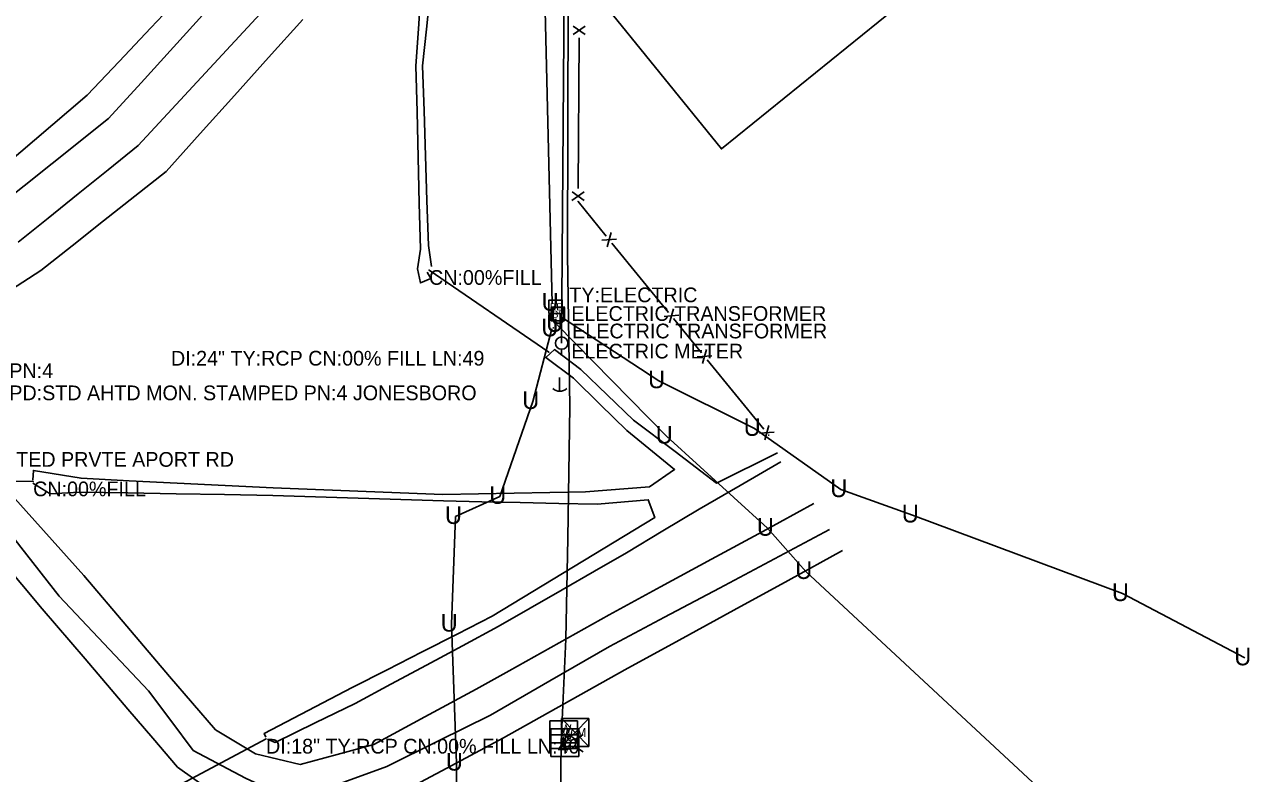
# Model space of a CAD drawing. Extents: x 1707085 to 1720058, y 548761 to 560063.
# Drawn here: x 1712315.3 to 1712731.2, y 549372.3 to 549626.7 of the extents above; entities that cross this region are included whole.
import ezdxf

# ---------------------------------------------------------------- set-up
doc = ezdxf.new("R2010")
doc.units = 0
for name, color, linetype in [('3', 7, 'Continuous'), ('Default', 7, 'Continuous'), ('R_Contours', 7, 'Continuous'), ('R_Water Annot', 7, 'Continuous'), ('S_BUILDING', 7, 'Continuous'), ('S_DRG_PT_SYM', 7, 'Continuous'), ('S_EDGE_PAVEMENT', 7, 'Continuous'), ('S_ELECTRIC_UTILITIES', 7, 'Continuous'), ('S_MISC_STRUCTURES_ANNOT', 7, 'Continuous'), ('S_MSC_PT_SYM', 7, 'Continuous'), ('S_PAVEMENT_CROWN', 7, 'Continuous'), ('S_PRIMARY_CTL_ANNOT', 7, 'Continuous'), ('S_SIDE_DRAIN_ANNOT', 7, 'Continuous'), ('S_STR_PT_SYM', 7, 'Continuous'), ('S_SURVEY_TEXT_ANNOT', 7, 'Continuous'), ('S_UNDERGROUND_CABLE', 7, 'Continuous'), ('S_UNDERGROUND_CABLE_ANNOT', 7, 'Continuous'), ('S_UTILITY_POLE', 7, 'Continuous'), ('S_UTL_PT_SYM', 7, 'Continuous')]:
    doc.layers.add(name, color=color, linetype=linetype)

msp = doc.modelspace()

# ---------------------------------------------------------------- linework, layer by layer
for points in [[(1712477.33, 549715.78), (1712472.54, 549696.84), (1712465.4, 549684), (1712458.27, 549671.17), (1712452.94, 549675.14), (1712451.45, 549674.62), (1712451.65, 549662.89), (1712450.79, 549650.32), (1712449.93, 549637.76), (1712449.06, 549625.19), (1712448.2, 549612.62), (1712448.59, 549597.08), (1712448.99, 549581.53), (1712449.38, 549565.99), (1712449.77, 549550.44), (1712448.78, 549543.69), (1712449.73, 549538.92), (1712453.33, 549540.43), (1712452.04, 549542.59)], [(1712482.85, 549714.24), (1712476.5, 549696.41), (1712466.06, 549679.47), (1712455.63, 549662.54), (1712454.35, 549650.06), (1712453.07, 549637.58), (1712451.79, 549625.11), (1712450.51, 549612.63), (1712451, 549597.38), (1712451.49, 549582.13), (1712451.98, 549566.87), (1712452.48, 549551.62), (1712453.51, 549544.5)], [(1712369.03, 549636.94), (1712358.25, 549625.52), (1712347.46, 549614.09), (1712336.67, 549602.67), (1712318.76, 549587.45), (1712300.85, 549572.22)], [(1712318.16, 549471.87), (1712318.37, 549475.26), (1712334.57, 549472.55), (1712350.86, 549471.75), (1712367.16, 549470.95), (1712383.46, 549470.15), (1712399.76, 549469.35), (1712414.15, 549468.78), (1712428.54, 549468.2), (1712442.93, 549467.63), (1712457.32, 549467.06), (1712481.54, 549467.54), (1712505.76, 549468.01), (1712527.51, 549469.62), (1712536.03, 549475.56), (1712519.8, 549488.74), (1712510.74, 549497.64), (1712501.67, 549506.55), (1712492.28, 549513.55), (1712495.32, 549516.26), (1712504.19, 549509.48), (1712522.12, 549492.35), (1712536.2, 549481.64), (1712550.27, 549470.93), (1712571.02, 549481.17)], [(1712572.1, 549478.15), (1712558.27, 549470.1), (1712544.43, 549462.04), (1712532.07, 549454.66), (1712519.7, 549447.29), (1712508.81, 549441.01), (1712497.91, 549434.73), (1712487.02, 549428.45), (1712476.13, 549422.17), (1712464, 549415.65), (1712451.87, 549409.13), (1712439.74, 549402.61), (1712427.62, 549396.1), (1712414.02, 549389.48), (1712400.42, 549382.86), (1712397.78, 549383.93)], [(1712318.21, 549470.9), (1712324.01, 549467.32), (1712334.01, 549467.9), (1712350.42, 549467.6), (1712366.83, 549467.31), (1712383.23, 549467.01), (1712399.64, 549466.72), (1712414.11, 549466.27), (1712428.59, 549465.82), (1712443.07, 549465.37), (1712457.54, 549464.92), (1712470.59, 549464.62), (1712483.64, 549464.33), (1712496.69, 549464.04), (1712509.74, 549463.75), (1712527.1, 549465.27), (1712529.29, 549459.19), (1712515.51, 549450.81), (1712501.73, 549442.44), (1712487.94, 549434.06), (1712474.16, 549425.68), (1712462.28, 549419.64), (1712450.39, 549413.6), (1712438.5, 549407.56), (1712426.61, 549401.53), (1712411.65, 549393.7), (1712396.69, 549385.87), (1712397.31, 549384.67)]]:
    msp.add_lwpolyline(points)
at = {"layer": '3'}
for p, q in [((1712493.34, 549515.39), (1712452.67, 549543.27)), ((1712273.3, 549472.1), (1712318.27, 549471.46)), ((1712397.33, 549384.07), (1712361.92, 549365.14))]:
    msp.add_line(p, q, dxfattribs=at)
at = {"layer": 'R_Contours'}
for p, q in [((1712505.68, 549626.11), (1712501.57, 549623.27)), ((1712501.59, 549626.14), (1712505.66, 549623.25)), ((1712505.32, 549569.81), (1712501.21, 549566.97)), ((1712501.23, 549569.83), (1712505.31, 549566.94)), ((1712514.5, 549556.02), (1712513.14, 549551.21)), ((1712511.32, 549553.43), (1712516.31, 549553.8)), ((1712535.62, 549530.14), (1712534.26, 549525.33)), ((1712532.45, 549527.55), (1712537.43, 549527.92)), ((1712543.7, 549513.76), (1712548.68, 549514.13)), ((1712546.87, 549516.35), (1712545.51, 549511.54)), ((1712564.82, 549487.88), (1712569.8, 549488.25)), ((1712567.99, 549490.47), (1712566.63, 549485.66))]:
    msp.add_line(p, q, dxfattribs=at)
for points in [[(1712503.61, 549622.13), (1712503.28, 549570.95)], [(1712503.26, 549566.55), (1712512.86, 549554.79)], [(1712514.78, 549552.44), (1712533.98, 549528.91)], [(1712535.63, 549526.89), (1712545.23, 549515.12)], [(1712547.15, 549512.77), (1712566.35, 549489.24)]]:
    msp.add_lwpolyline(points, dxfattribs=at)
at = {"layer": 'R_Water Annot'}
for p, q in [((1712499.89, 549641.55), (1712499.65, 549548.57)), ((1712499.65, 549548.57), (1712500.51, 549496.81)), ((1712500.51, 549496.81), (1712499.75, 549452.23)), ((1712499.75, 549452.23), (1712499.07, 549417.92)), ((1712499.07, 549417.92), (1712497.57, 549383.08)), ((1712493.7, 549390.15), (1712503.12, 549390.15)), ((1712493.7, 549380.73), (1712493.7, 549390.15)), ((1712497.62, 549390.95), (1712506.96, 549390.95)), ((1712497.62, 549390.95), (1712497.62, 549381.46)), ((1712497.62, 549390.95), (1712506.96, 549381.46)), ((1712506.96, 549390.95), (1712497.62, 549381.46)), ((1712503.12, 549390.15), (1712503.12, 549380.73)), ((1712506.96, 549390.95), (1712506.96, 549381.46)), ((1712493.7, 549385.46), (1712503.12, 549385.46)), ((1712494.07, 549387.43), (1712503.48, 549387.43)), ((1712494.07, 549378.02), (1712494.07, 549387.43)), ((1712502.19, 549383.85), (1712505.01, 549385.58)), ((1712503.48, 549387.43), (1712503.48, 549378.02)), ((1712503.12, 549380.73), (1712493.7, 549380.73)), ((1712494.07, 549382.74), (1712503.48, 549382.74)), ((1712497.57, 549383.08), (1712496.4, 549273.84)), ((1712497.62, 549381.46), (1712506.96, 549381.46)), ((1712502.07, 549381.54), (1712504.98, 549379.61)), ((1712503.48, 549378.02), (1712494.07, 549378.02))]:
    msp.add_line(p, q, dxfattribs=at)
msp.add_circle((1712500.29, 549382.79), 2.18, dxfattribs=at)
at = {"layer": 'S_BUILDING'}
for p, q in [((1712551.91, 549584.43), (1712648.77, 549662.87)), ((1712508.82, 549637.74), (1712551.91, 549584.43))]:
    msp.add_line(p, q, dxfattribs=at)
at = {"layer": 'S_DRG_PT_SYM'}
for points in [[(1712452.67, 549543.27), (1712452.67, 549543.32), (1712452.67, 549543.27), (1712452.62, 549543.27), (1712452.67, 549543.27), (1712452.67, 549543.22), (1712452.67, 549543.27), (1712452.72, 549543.27)], [(1712493.34, 549515.39), (1712493.34, 549515.44), (1712493.34, 549515.39), (1712493.29, 549515.39), (1712493.34, 549515.39), (1712493.34, 549515.34), (1712493.34, 549515.39), (1712493.39, 549515.39)], [(1712318.27, 549471.46), (1712318.27, 549471.51), (1712318.27, 549471.46), (1712318.22, 549471.46), (1712318.27, 549471.46), (1712318.27, 549471.41), (1712318.27, 549471.46), (1712318.32, 549471.46)], [(1712397.33, 549384.07), (1712397.33, 549384.12), (1712397.33, 549384.07), (1712397.28, 549384.07), (1712397.33, 549384.07), (1712397.33, 549384.02), (1712397.33, 549384.07), (1712397.38, 549384.07)]]:
    msp.add_lwpolyline(points, dxfattribs=at)
at = {"layer": 'S_EDGE_PAVEMENT'}
for points in [[(1712376.86, 549631.06), (1712365.88, 549618.95), (1712354.89, 549606.84), (1712343.9, 549594.73), (1712324.74, 549579.52), (1712305.58, 549564.31)], [(1712376.86, 549631.06), (1712365.88, 549618.95), (1712354.89, 549606.84), (1712343.9, 549594.73), (1712324.74, 549579.52), (1712305.58, 549564.31)], [(1712409.78, 549628.4), (1712398.19, 549615.5), (1712386.6, 549602.6), (1712375.02, 549589.7), (1712363.43, 549576.8), (1712352.81, 549568.38), (1712342.19, 549559.96), (1712331.56, 549551.54), (1712320.94, 549543.12), (1712308.7, 549535.18)], [(1712409.78, 549628.4), (1712398.19, 549615.5), (1712386.6, 549602.6), (1712375.02, 549589.7), (1712363.43, 549576.8), (1712352.81, 549568.38), (1712342.19, 549559.96), (1712331.56, 549551.54), (1712320.94, 549543.12), (1712308.7, 549535.18)], [(1712296.46, 549526.84), (1712292.01, 549520.42), (1712290.52, 549506), (1712295.1, 549484.36), (1712308.08, 549470.06), (1712321.8, 549454.8), (1712335.53, 549439.55), (1712350.04, 549422.39), (1712364.55, 549405.24), (1712380.17, 549387.13), (1712393.81, 549378.95), (1712408.98, 549375.38), (1712421.46, 549378.78), (1712433.94, 549382.18), (1712451.28, 549391.53), (1712468.62, 549400.89), (1712479.92, 549407.22), (1712491.22, 549413.56), (1712502.51, 549419.9), (1712513.81, 549426.24), (1712531.2, 549435.67), (1712548.58, 549445.1), (1712565.97, 549454.53), (1712583.35, 549463.96)], [(1712223.72, 549498.51), (1712229.13, 549498.44), (1712241.24, 549493.44), (1712253.34, 549488.44), (1712265.45, 549483.43), (1712277.56, 549478.43), (1712293.69, 549461.21), (1712307.52, 549444.74), (1712321.35, 549428.27), (1712335.89, 549411.22), (1712350.42, 549394.17), (1712358.86, 549384.32), (1712367.29, 549374.48), (1712384.89, 549361.9)], [(1712442.74, 549365.6), (1712460.36, 549375), (1712477.98, 549384.39), (1712498.56, 549395.92), (1712519.14, 549407.45), (1712537.63, 549417.59), (1712556.11, 549427.73), (1712574.59, 549437.88), (1712593.07, 549448.02)]]:
    msp.add_lwpolyline(points, dxfattribs=at)
at = {"layer": 'S_ELECTRIC_UTILITIES'}
for points in [[(1712493.38, 549528.57), (1712493.38, 549533.07), (1712497.88, 549533.07), (1712497.88, 549528.57)], [(1712494.14, 549526.05), (1712494.14, 549530.55), (1712498.64, 549530.55), (1712498.64, 549526.05)]]:
    msp.add_lwpolyline(points, close=True, dxfattribs=at)
at = {"layer": 'S_MSC_PT_SYM'}
for points in [[(1712503.26, 549566.55), (1712503.26, 549566.6), (1712503.26, 549566.55), (1712503.21, 549566.55), (1712503.26, 549566.55), (1712503.26, 549566.5), (1712503.26, 549566.55), (1712503.31, 549566.55)], [(1712494.65, 549530.72), (1712494.65, 549530.77), (1712494.65, 549530.72), (1712494.6, 549530.72), (1712494.65, 549530.72), (1712494.65, 549530.67), (1712494.65, 549530.72), (1712494.7, 549530.72)], [(1712495.21, 549525.37), (1712495.21, 549525.42), (1712495.21, 549525.37), (1712495.16, 549525.37), (1712495.21, 549525.37), (1712495.21, 549525.32), (1712495.21, 549525.37), (1712495.26, 549525.37)], [(1712494.84, 549523.64), (1712494.84, 549523.69), (1712494.84, 549523.64), (1712494.79, 549523.64), (1712494.84, 549523.64), (1712494.84, 549523.59), (1712494.84, 549523.64), (1712494.89, 549523.64)], [(1712568, 549487.22), (1712568, 549487.27), (1712568, 549487.22), (1712567.95, 549487.22), (1712568, 549487.22), (1712568, 549487.17), (1712568, 549487.22), (1712568.05, 549487.22)]]:
    msp.add_lwpolyline(points, dxfattribs=at)
at = {"layer": 'S_PAVEMENT_CROWN'}
for points in [[(1712399.65, 549634.97), (1712388.21, 549622.61), (1712376.78, 549610.25), (1712365.34, 549597.89), (1712353.91, 549585.54), (1712343.72, 549577.35), (1712333.53, 549569.16), (1712323.33, 549560.97), (1712313.14, 549552.79)], [(1712399.65, 549634.97), (1712388.21, 549622.61), (1712376.78, 549610.25), (1712365.34, 549597.89), (1712353.91, 549585.54), (1712343.72, 549577.35), (1712333.53, 549569.16), (1712323.33, 549560.97), (1712313.14, 549552.79)], [(1712262.08, 549508.97), (1712273.19, 549495.92), (1712284.3, 549482.88), (1712301.14, 549465.86), (1712314.12, 549449.22), (1712327.1, 549432.57), (1712342.27, 549416.46), (1712357.44, 549400.34), (1712365.03, 549390.24), (1712372.63, 549380.14), (1712390.32, 549370.7), (1712406.74, 549363.12), (1712422.56, 549368.89), (1712438.39, 549374.65), (1712455.94, 549383.35), (1712473.5, 549392.05), (1712493.73, 549403.76), (1712513.96, 549415.46), (1712532.63, 549425.37), (1712551.3, 549435.29), (1712569.98, 549445.2), (1712588.65, 549455.12)]]:
    msp.add_lwpolyline(points, dxfattribs=at)
at = {"layer": 'S_STR_PT_SYM'}
msp.add_lwpolyline([(1712551.91, 549584.43), (1712551.91, 549584.48), (1712551.91, 549584.43), (1712551.86, 549584.43), (1712551.91, 549584.43), (1712551.91, 549584.38), (1712551.91, 549584.43), (1712551.96, 549584.43)], dxfattribs=at)
at = {"layer": 'S_UNDERGROUND_CABLE'}
for p, q in [((1712491.97, 549639.04), (1712494.52, 549532.03)), ((1712530.66, 549505.69), (1712497.32, 549527.54)), ((1712487.93, 549498.63), (1712494.42, 549523.3)), ((1712533.28, 549486.87), (1712496.07, 549524.85)), ((1712563.14, 549489.52), (1712530.66, 549505.69)), ((1712476.72, 549466.43), (1712487.93, 549498.63)), ((1712592.52, 549468.71), (1712563.14, 549489.52)), ((1712567.6, 549455.59), (1712533.28, 549486.87)), ((1712616.79, 549460.09), (1712592.52, 549468.71)), ((1712461.7, 549459.61), (1712476.72, 549466.43)), ((1712460.25, 549423.04), (1712461.7, 549459.61)), ((1712688.13, 549433.4), (1712616.79, 549460.09)), ((1712580.62, 549440.92), (1712567.6, 549455.59)), ((1712659.13, 549367.93), (1712580.62, 549440.92)), ((1712729.67, 549411.59), (1712688.13, 549433.4)), ((1712462.01, 549375.82), (1712460.25, 549423.04)), ((1712462.29, 549293.82), (1712462.01, 549375.82))]:
    msp.add_line(p, q, dxfattribs=at)
at = {"layer": 'S_UTILITY_POLE'}
for p, q in [((1712497.68, 549520.56), (1712497.68, 549522.69)), ((1712497.68, 549516.34), (1712497.68, 549514.29)), ((1712496.99, 549506.85), (1712496.99, 549502.12))]:
    msp.add_line(p, q, dxfattribs=at)
msp.add_lwpolyline([(1712497.7, 549518.48), (1712500.91, 549949.57), (1712500.58, 550149.34), (1712502.49, 550416.34), (1712509.79, 550634.49), (1712512.76, 550903.53), (1712513.37, 551033.49), (1712513.87, 551133.13), (1712444.45, 551132.54)], dxfattribs=at)
msp.add_circle((1712497.7, 549518.48), 2.11, dxfattribs=at)
msp.add_arc((1712497.05, 549505.54), 3.41, 226.3972, 313.6028, dxfattribs=at)
at = {"layer": 'S_UTL_PT_SYM'}
for points in [[(1712499.65, 549548.57), (1712499.65, 549548.62), (1712499.65, 549548.57), (1712499.6, 549548.57), (1712499.65, 549548.57), (1712499.65, 549548.52), (1712499.65, 549548.57), (1712499.7, 549548.57)], [(1712500.51, 549496.81), (1712500.51, 549496.86), (1712500.51, 549496.81), (1712500.46, 549496.81), (1712500.51, 549496.81), (1712500.51, 549496.76), (1712500.51, 549496.81), (1712500.56, 549496.81)], [(1712499.75, 549452.23), (1712499.75, 549452.28), (1712499.75, 549452.23), (1712499.7, 549452.23), (1712499.75, 549452.23), (1712499.75, 549452.18), (1712499.75, 549452.23), (1712499.8, 549452.23)], [(1712499.07, 549417.92), (1712499.07, 549417.97), (1712499.07, 549417.92), (1712499.02, 549417.92), (1712499.07, 549417.92), (1712499.07, 549417.87), (1712499.07, 549417.92), (1712499.12, 549417.92)], [(1712497.57, 549383.08), (1712497.57, 549383.13), (1712497.57, 549383.08), (1712497.52, 549383.08), (1712497.57, 549383.08), (1712497.57, 549383.03), (1712497.57, 549383.08), (1712497.62, 549383.08)]]:
    msp.add_lwpolyline(points, dxfattribs=at)

# ---------------------------------------------------------------- texts
at = {"layer": 'Default'}
for p in [(1712490.89, 549529.48), (1712493.69, 549524.99), (1712490.79, 549520.76), (1712492.44, 549522.3), (1712527.03, 549503.15), (1712484.3, 549496.09), (1712559.51, 549486.98), (1712529.65, 549484.33), (1712588.89, 549466.17), (1712473.09, 549463.88), (1712458.07, 549457.06), (1712613.17, 549457.55), (1712563.97, 549453.05), (1712576.99, 549438.37), (1712684.5, 549430.85), (1712456.62, 549420.49), (1712726.04, 549409.04), (1712458.38, 549373.28)]:
    msp.add_text('U', height=6, rotation=360, dxfattribs=at).set_placement(p)
at = {"layer": 'R_Water Annot'}
for s, p in [('W', (1712497.25, 549385.99)), ('V', (1712497.49, 549381.93)), ('W', (1712497.62, 549383.27)), ('W M', (1712497.83, 549384.72)), ('V', (1712497.85, 549379.21))]:
    msp.add_text(s, height=3, rotation=360, dxfattribs=at).set_placement(p)
at = {"layer": 'S_ELECTRIC_UTILITIES'}
for p in [(1712493.7, 549529.62), (1712494.46, 549527.1)]:
    msp.add_text('BE', height=2.4, rotation=360, dxfattribs=at).set_placement(p)
at = {"layer": 'S_MISC_STRUCTURES_ANNOT'}
for s, p in [('ELECTRIC TRANSFORMER', (1712500.97, 549526.02)), ('ELECTRIC TRANSFORMER', (1712501.28, 549520.09)), ('ELECTRIC METER', (1712500.98, 549513.25))]:
    msp.add_text(s, height=5, dxfattribs=at).set_placement(p)
at = {"layer": 'S_PRIMARY_CTL_ANNOT'}
for s, p in [('PN:4', (1712310.19, 549506.58)), ('PD:STD AHTD MON. STAMPED PN:4 JONESBORO', (1712310.19, 549499.08))]:
    msp.add_text(s, height=5, dxfattribs=at).set_placement(p)
at = {"layer": 'S_SIDE_DRAIN_ANNOT'}
for s, p in [('CN:00%FILL', (1712452.67, 549538.27)), ('DI:24" TY:RCP CN:00% FILL LN:49', (1712365.06, 549510.84)), ('CN:00%FILL', (1712318.27, 549466.46)), ('DI:18" TY:RCP CN:00% FILL LN:40', (1712397.33, 549379.07))]:
    msp.add_text(s, height=5, dxfattribs=at).set_placement(p)
at = {"layer": 'S_SURVEY_TEXT_ANNOT'}
msp.add_text('RESTRICTED PRVTE APORT RD', height=5, dxfattribs=at).set_placement((1712283.17, 549476.47))
at = {"layer": 'S_UNDERGROUND_CABLE_ANNOT'}
msp.add_text('TY:ELECTRIC', height=5, dxfattribs=at).set_placement((1712500.32, 549532.36))

doc.saveas('drawing.dxf')
